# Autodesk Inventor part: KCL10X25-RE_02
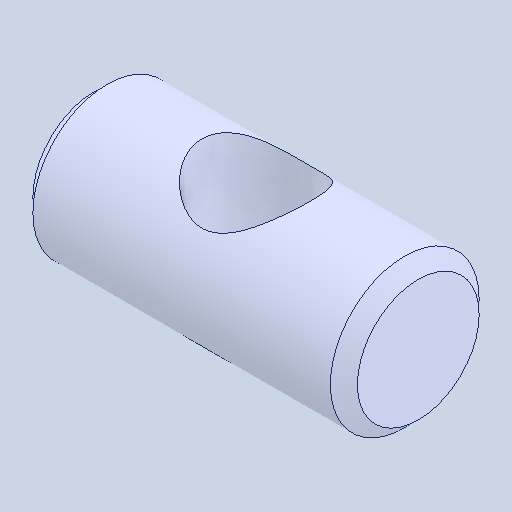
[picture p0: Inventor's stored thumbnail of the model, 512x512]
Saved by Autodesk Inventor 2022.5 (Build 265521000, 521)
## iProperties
Created: 2024-08
Part Number: KCL10X25-RE_02
Material: 一般
Document SubType Name: Modeling
Designer: ImaoCorp
Density: 1 g/cm^3
Appearance: 既定
Author: ImaoCorp
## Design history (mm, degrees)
feature "KCL10X25-RE_02"
node "ソリッド1"
